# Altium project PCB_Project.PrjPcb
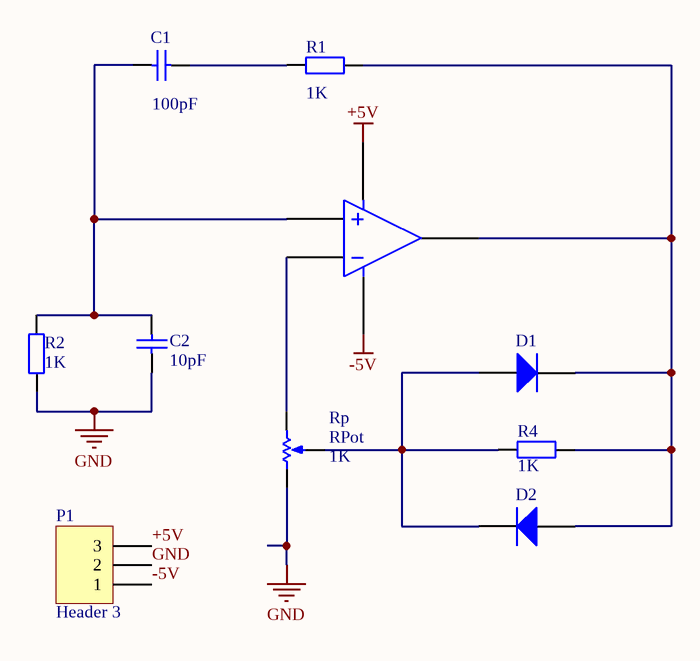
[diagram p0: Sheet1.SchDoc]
1 sheet, 10 parts. Net scope: global (net labels, ports and power ports of the same name join across sheets).
Board file: PCB1.PcbDoc

## Sheet Sheet1.SchDoc
size A4

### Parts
C1  value 100pF  [RAD-0.3]  (hidden comment: Cap)
C2  value 10pF  [RAD-0.3]  (hidden comment: Cap)
D1  Diode  [SMC]  (value not drawn)
D2  Diode  [SMC]  (value not drawn)
F1  1458  [DIP-8]  (value not drawn)  (part A of 2)
P1  Header 3  [HDR1X3]
R1  value 1K  [AXIAL-0.4]  (hidden comment: Res2)
R2  value 1K  [AXIAL-0.4]  (hidden comment: Res2)
R4  value 1K  [AXIAL-0.4]  (hidden comment: Res2)
Rp  RPot  value 1K  [VR5]

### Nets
+5V: F1.8 P1.3
-5V: F1.4 P1.1
GND: C2.1 P1.2 R2.1 Rp.1(TOP)
NetC1_1: C1.1 C2.2 F1.3 R2.2
NetC1_2: C1.2 R1.1
NetD1_1: D1.1(A) D2.2(K) R4.1 Rp.3(TAP)
NetD1_2: D1.2(K) D2.1(A) F1.1 R1.2 R4.2
NetF1_2: F1.2 Rp.2(BOT)

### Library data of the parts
C1 C2 = Cap: Capacitor
D1 D2 = Diode: Default Diode
P1 = Header 3: Header, 3-Pin
R1 R2 R4 = Res2: Resistor
Rp = RPot: Potentiometer; Sim Note: Enter the Resistance value and the set point into parameter fields.; Set Position: 0.5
